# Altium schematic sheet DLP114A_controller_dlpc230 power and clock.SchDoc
size 558 x 431 mm; Date: Not shown in title block; ApprovedBy: Not shown in title block; CheckedBy: Not shown in title block; Author: Not shown in title block; CompanyName: Not shown in title block; Engineer: Not shown in title block; Organization: Not shown in title block; Address1: Not shown in title block; Address2: Not shown in title block; Address3: Not shown in title block; Address4: Not shown in title block; DocumentNumber: 2; Revision: Use project parameter SCH_Rev; SheetNumber: 2; SheetTotal: 7; PageSetup: Record=PageOptions¦CenterHorizontal=True¦CenterVertical=True¦PrintScale=0.69¦XCorrection=1.00¦YCorrection=1.00¦PrintKind=0¦BorderSize=5000000¦LeftOffset=0¦BottomOffset=0¦Orientation=2¦PaperLength=1000¦PaperWidth=1000¦Scale=100¦PaperSource=15¦PrintQuality=600¦MediaType=1¦DitherType=10¦PaperKind=Letter¦PrintScaleMode=1
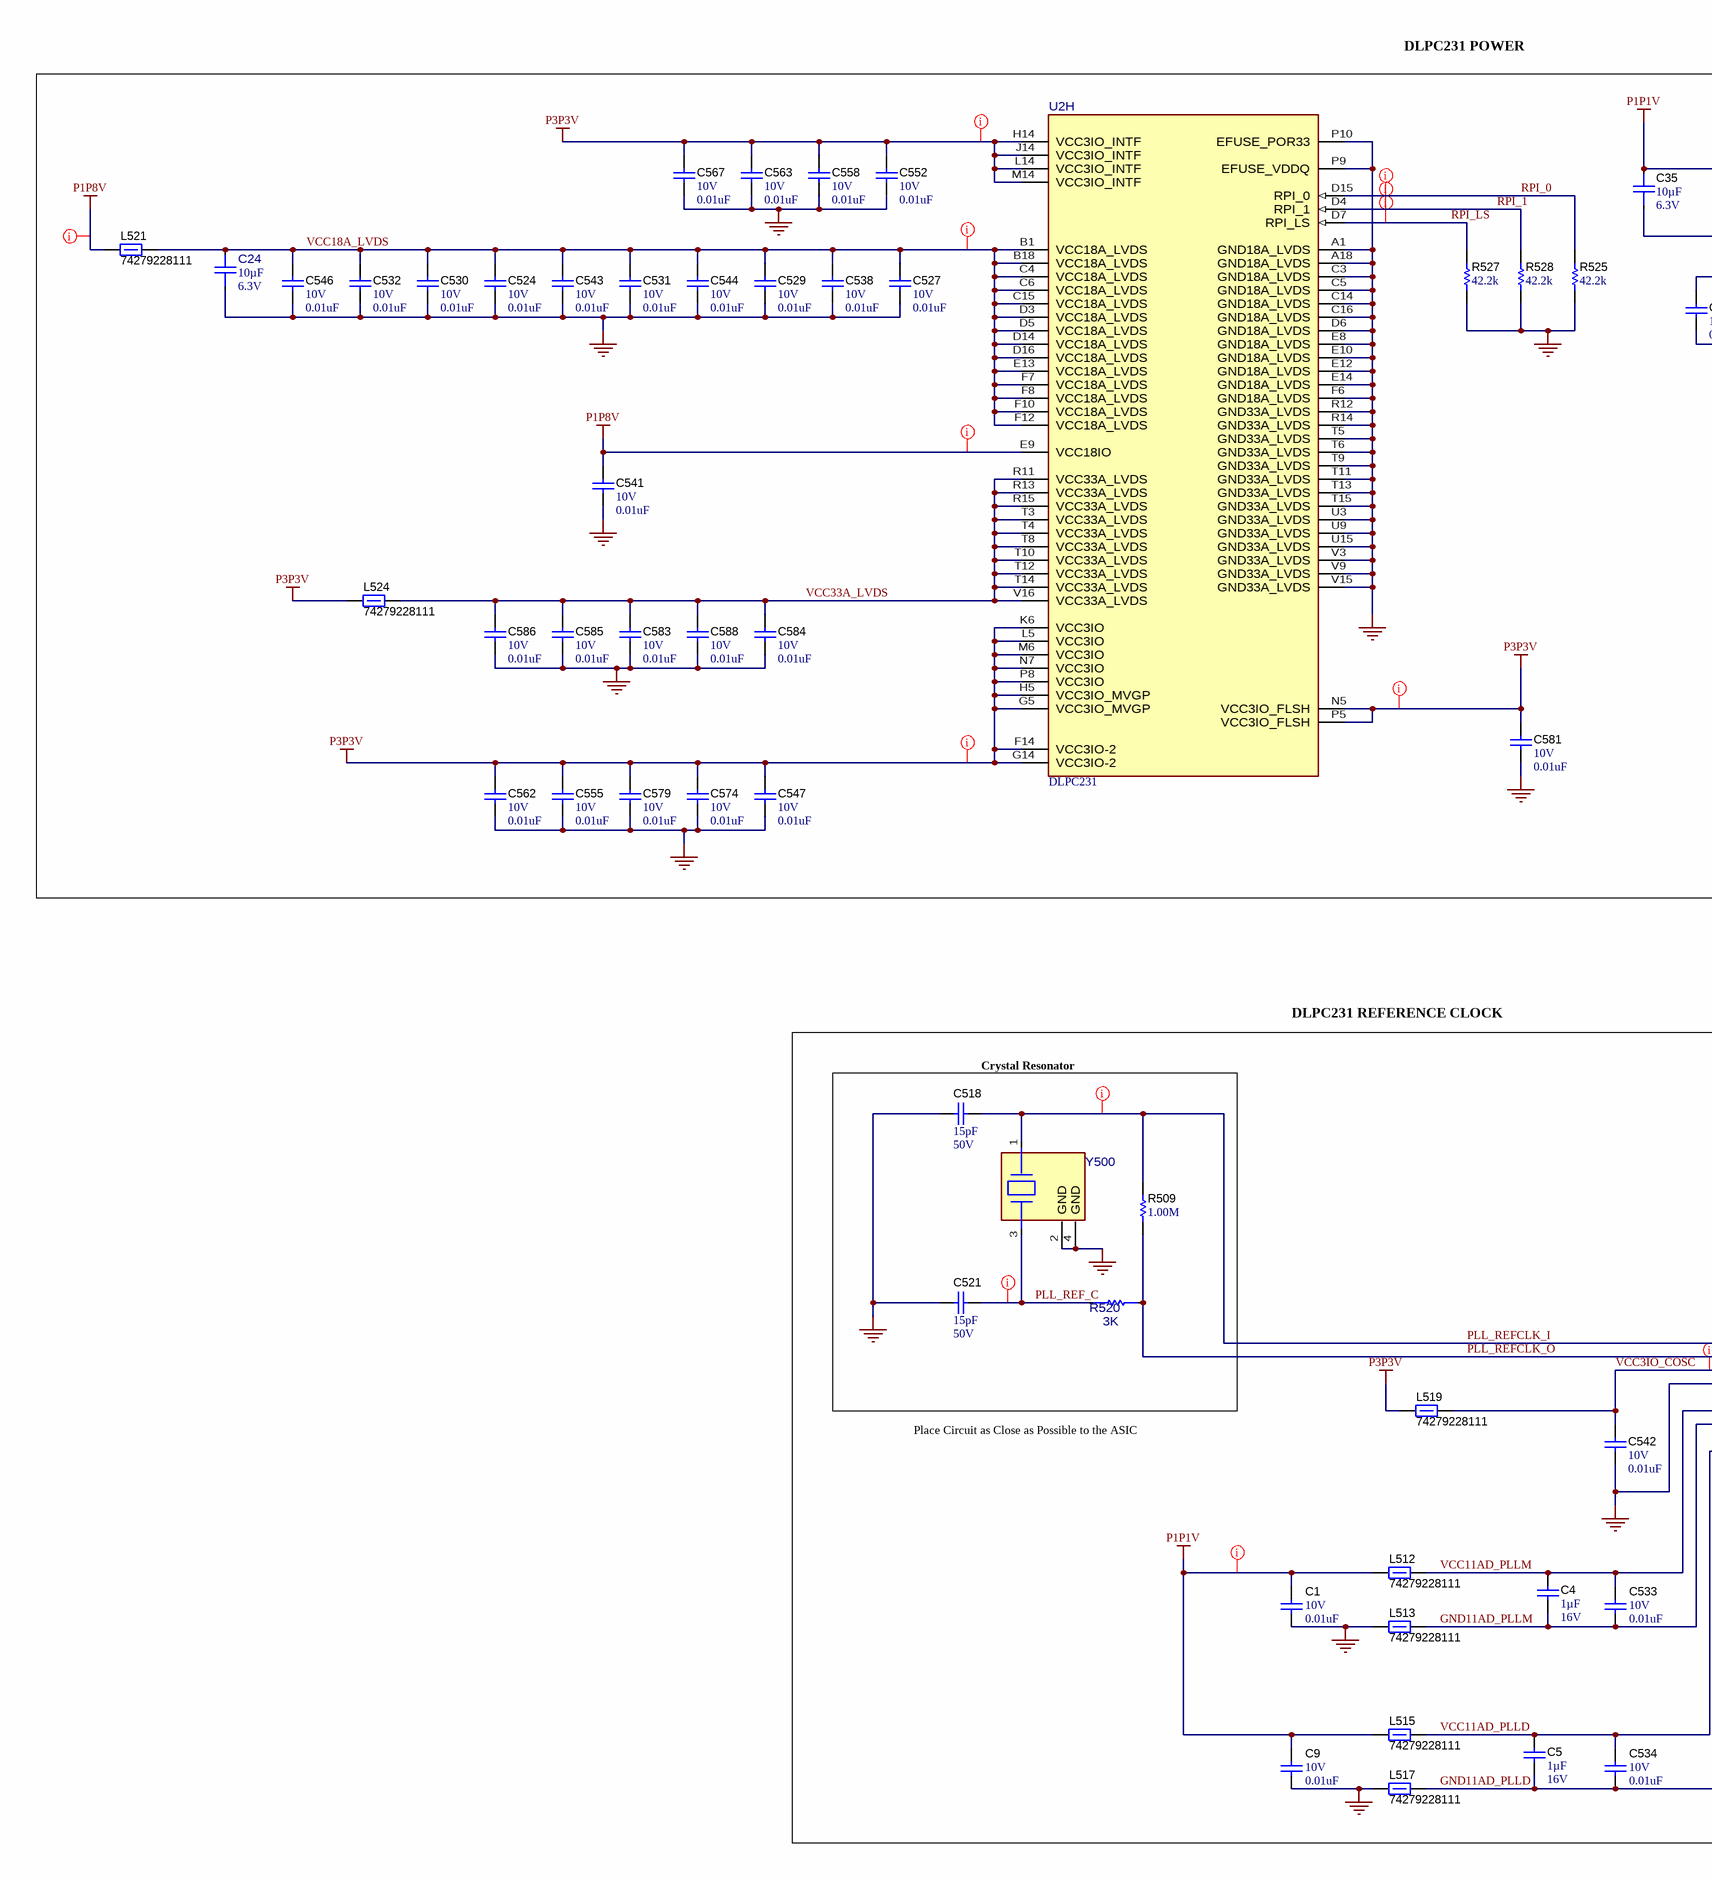
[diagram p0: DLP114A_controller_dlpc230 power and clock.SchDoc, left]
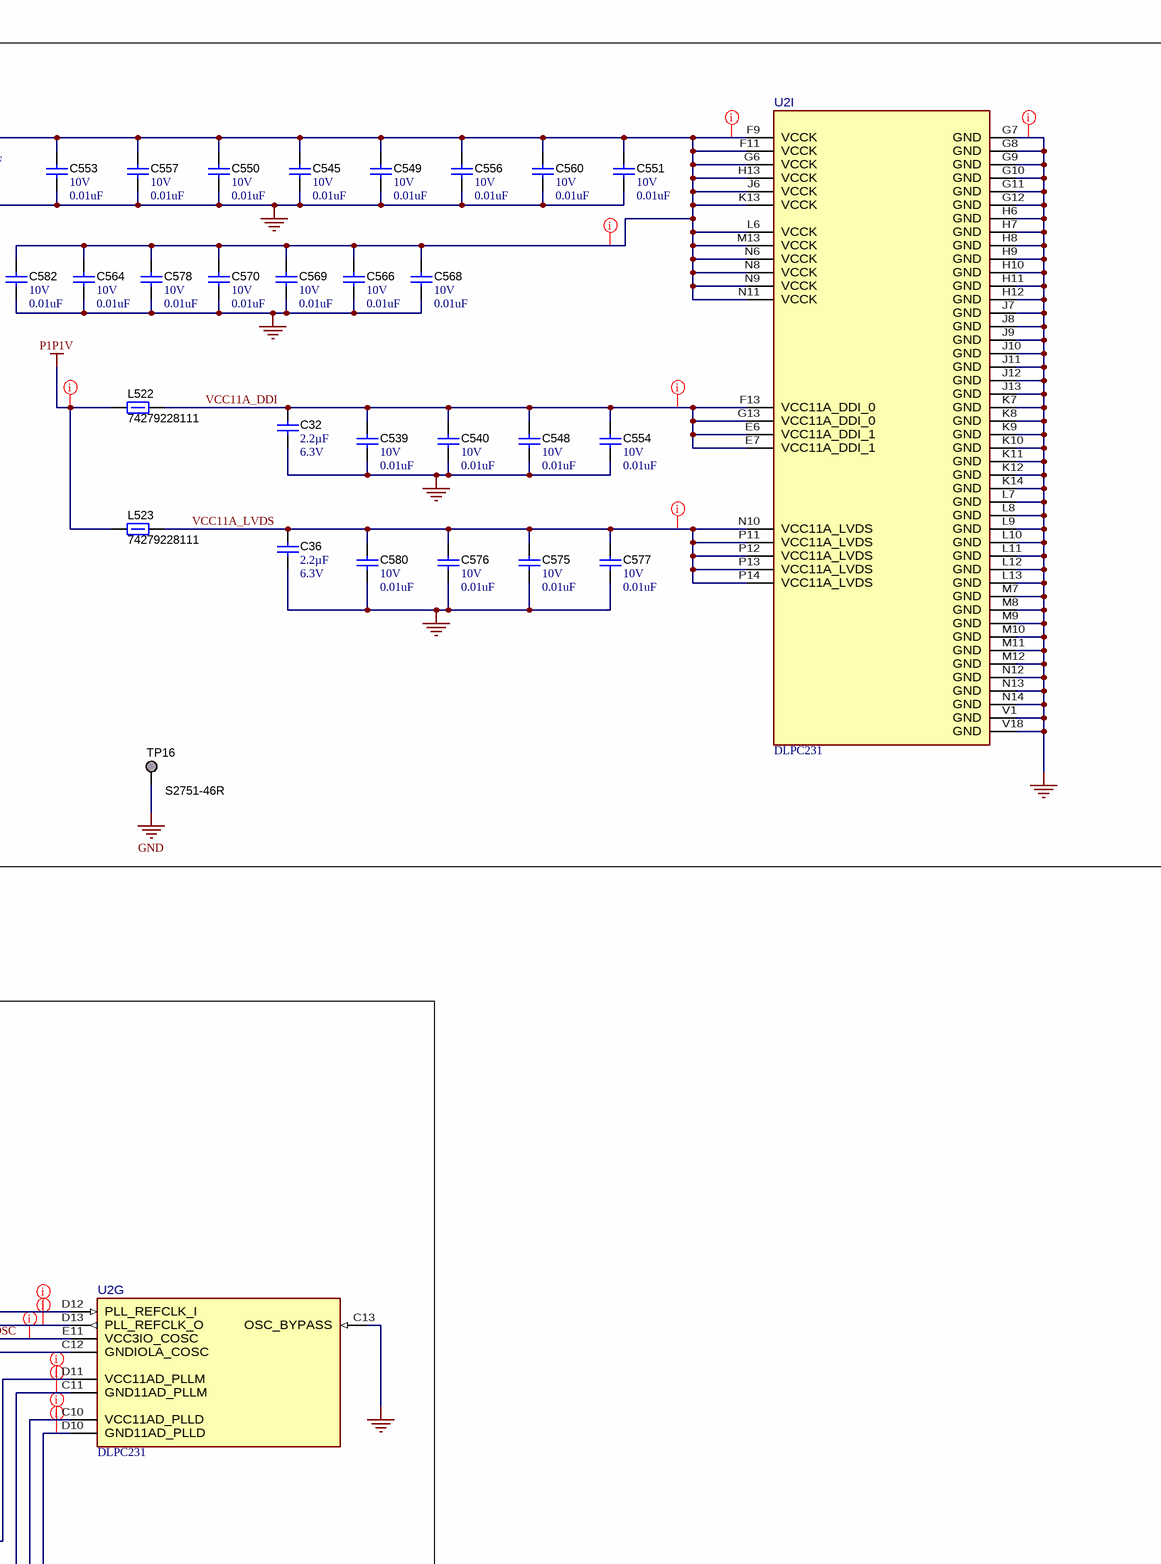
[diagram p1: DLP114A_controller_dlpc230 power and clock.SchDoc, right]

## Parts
C1  VDC_V: 10V  ValueDisplayed: 0.01uF  [0201_033]  (hidden comment: CGA1A2X7R1A103K030BA)
C4  Cap_F: 1µF  VDC_V: 16V  [0603]  (hidden comment: GCM188R71C105KA64D)
C5  Cap_F: 1µF  VDC_V: 16V  [0603]  (hidden comment: GCM188R71C105KA64D)
C9  VDC_V: 10V  ValueDisplayed: 0.01uF  [0201_033]  (hidden comment: CGA1A2X7R1A103K030BA)
C24  Cap_F: 10µF  VDC_V: 6.3V  [FP-CGA4J1X7R0J106K125AC_0805-MFG]  (hidden comment: CGA4J1X7R0J106K125AC)
C32  Cap_F: 2.2µF  VDC_V: 6.3V  [0603]  (hidden comment: GCM188R70J225KE22D)
C35  Cap_F: 10µF  VDC_V: 6.3V  [FP-CGA4J1X7R0J106K125AC_0805-MFG]  (hidden comment: CGA4J1X7R0J106K125AC)
C36  Cap_F: 2.2µF  VDC_V: 6.3V  [0603]  (hidden comment: GCM188R70J225KE22D)
C518  ValueDisplayed: 15pF  VDC_V: 50V  [0402]  (hidden comment: CGA2B2C0G1H150J050BA)
C521  ValueDisplayed: 15pF  VDC_V: 50V  [0402]  (hidden comment: CGA2B2C0G1H150J050BA)
C524  VDC_V: 10V  ValueDisplayed: 0.01uF  [0201_033]  (hidden comment: CGA1A2X7R1A103K030BA)
C527  VDC_V: 10V  ValueDisplayed: 0.01uF  [0201_033]  (hidden comment: CGA1A2X7R1A103K030BA)
C529  VDC_V: 10V  ValueDisplayed: 0.01uF  [0201_033]  (hidden comment: CGA1A2X7R1A103K030BA)
C530  VDC_V: 10V  ValueDisplayed: 0.01uF  [0201_033]  (hidden comment: CGA1A2X7R1A103K030BA)
C531  VDC_V: 10V  ValueDisplayed: 0.01uF  [0201_033]  (hidden comment: CGA1A2X7R1A103K030BA)
C532  VDC_V: 10V  ValueDisplayed: 0.01uF  [0201_033]  (hidden comment: CGA1A2X7R1A103K030BA)
C533  VDC_V: 10V  ValueDisplayed: 0.01uF  [0201_033]  (hidden comment: CGA1A2X7R1A103K030BA)
C534  VDC_V: 10V  ValueDisplayed: 0.01uF  [0201_033]  (hidden comment: CGA1A2X7R1A103K030BA)
C538  VDC_V: 10V  ValueDisplayed: 0.01uF  [0201_033]  (hidden comment: CGA1A2X7R1A103K030BA)
C539  VDC_V: 10V  ValueDisplayed: 0.01uF  [0201_033]  (hidden comment: CGA1A2X7R1A103K030BA)
C540  VDC_V: 10V  ValueDisplayed: 0.01uF  [0201_033]  (hidden comment: CGA1A2X7R1A103K030BA)
C541  VDC_V: 10V  ValueDisplayed: 0.01uF  [0201_033]  (hidden comment: CGA1A2X7R1A103K030BA)
C542  VDC_V: 10V  ValueDisplayed: 0.01uF  [0201_033]  (hidden comment: CGA1A2X7R1A103K030BA)
C543  VDC_V: 10V  ValueDisplayed: 0.01uF  [0201_033]  (hidden comment: CGA1A2X7R1A103K030BA)
C544  VDC_V: 10V  ValueDisplayed: 0.01uF  [0201_033]  (hidden comment: CGA1A2X7R1A103K030BA)
C545  VDC_V: 10V  ValueDisplayed: 0.01uF  [0201_033]  (hidden comment: CGA1A2X7R1A103K030BA)
C546  VDC_V: 10V  ValueDisplayed: 0.01uF  [0201_033]  (hidden comment: CGA1A2X7R1A103K030BA)
C547  VDC_V: 10V  ValueDisplayed: 0.01uF  [0201_033]  (hidden comment: CGA1A2X7R1A103K030BA)
C548  VDC_V: 10V  ValueDisplayed: 0.01uF  [0201_033]  (hidden comment: CGA1A2X7R1A103K030BA)
C549  VDC_V: 10V  ValueDisplayed: 0.01uF  [0201_033]  (hidden comment: CGA1A2X7R1A103K030BA)
C550  VDC_V: 10V  ValueDisplayed: 0.01uF  [0201_033]  (hidden comment: CGA1A2X7R1A103K030BA)
C551  VDC_V: 10V  ValueDisplayed: 0.01uF  [0201_033]  (hidden comment: CGA1A2X7R1A103K030BA)
C552  VDC_V: 10V  ValueDisplayed: 0.01uF  [0201_033]  (hidden comment: CGA1A2X7R1A103K030BA)
C553  VDC_V: 10V  ValueDisplayed: 0.01uF  [0201_033]  (hidden comment: CGA1A2X7R1A103K030BA)
C554  VDC_V: 10V  ValueDisplayed: 0.01uF  [0201_033]  (hidden comment: CGA1A2X7R1A103K030BA)
C555  VDC_V: 10V  ValueDisplayed: 0.01uF  [0201_033]  (hidden comment: CGA1A2X7R1A103K030BA)
C556  VDC_V: 10V  ValueDisplayed: 0.01uF  [0201_033]  (hidden comment: CGA1A2X7R1A103K030BA)
C557  VDC_V: 10V  ValueDisplayed: 0.01uF  [0201_033]  (hidden comment: CGA1A2X7R1A103K030BA)
C558  VDC_V: 10V  ValueDisplayed: 0.01uF  [0201_033]  (hidden comment: CGA1A2X7R1A103K030BA)
C560  VDC_V: 10V  ValueDisplayed: 0.01uF  [0201_033]  (hidden comment: CGA1A2X7R1A103K030BA)
C562  VDC_V: 10V  ValueDisplayed: 0.01uF  [0201_033]  (hidden comment: CGA1A2X7R1A103K030BA)
C563  VDC_V: 10V  ValueDisplayed: 0.01uF  [0201_033]  (hidden comment: CGA1A2X7R1A103K030BA)
C564  VDC_V: 10V  ValueDisplayed: 0.01uF  [0201_033]  (hidden comment: CGA1A2X7R1A103K030BA)
C566  VDC_V: 10V  ValueDisplayed: 0.01uF  [0201_033]  (hidden comment: CGA1A2X7R1A103K030BA)
C567  VDC_V: 10V  ValueDisplayed: 0.01uF  [0201_033]  (hidden comment: CGA1A2X7R1A103K030BA)
C568  VDC_V: 10V  ValueDisplayed: 0.01uF  [0201_033]  (hidden comment: CGA1A2X7R1A103K030BA)
C569  VDC_V: 10V  ValueDisplayed: 0.01uF  [0201_033]  (hidden comment: CGA1A2X7R1A103K030BA)
C570  VDC_V: 10V  ValueDisplayed: 0.01uF  [0201_033]  (hidden comment: CGA1A2X7R1A103K030BA)
C574  VDC_V: 10V  ValueDisplayed: 0.01uF  [0201_033]  (hidden comment: CGA1A2X7R1A103K030BA)
C575  VDC_V: 10V  ValueDisplayed: 0.01uF  [0201_033]  (hidden comment: CGA1A2X7R1A103K030BA)
C576  VDC_V: 10V  ValueDisplayed: 0.01uF  [0201_033]  (hidden comment: CGA1A2X7R1A103K030BA)
C577  VDC_V: 10V  ValueDisplayed: 0.01uF  [0201_033]  (hidden comment: CGA1A2X7R1A103K030BA)
C578  VDC_V: 10V  ValueDisplayed: 0.01uF  [0201_033]  (hidden comment: CGA1A2X7R1A103K030BA)
C579  VDC_V: 10V  ValueDisplayed: 0.01uF  [0201_033]  (hidden comment: CGA1A2X7R1A103K030BA)
C580  VDC_V: 10V  ValueDisplayed: 0.01uF  [0201_033]  (hidden comment: CGA1A2X7R1A103K030BA)
C581  VDC_V: 10V  ValueDisplayed: 0.01uF  [0201_033]  (hidden comment: CGA1A2X7R1A103K030BA)
C582  VDC_V: 10V  ValueDisplayed: 0.01uF  [0201_033]  (hidden comment: CGA1A2X7R1A103K030BA)
C583  VDC_V: 10V  ValueDisplayed: 0.01uF  [0201_033]  (hidden comment: CGA1A2X7R1A103K030BA)
C584  VDC_V: 10V  ValueDisplayed: 0.01uF  [0201_033]  (hidden comment: CGA1A2X7R1A103K030BA)
C585  VDC_V: 10V  ValueDisplayed: 0.01uF  [0201_033]  (hidden comment: CGA1A2X7R1A103K030BA)
C586  VDC_V: 10V  ValueDisplayed: 0.01uF  [0201_033]  (hidden comment: CGA1A2X7R1A103K030BA)
C588  VDC_V: 10V  ValueDisplayed: 0.01uF  [0201_033]  (hidden comment: CGA1A2X7R1A103K030BA)
L512  74279228111  [0603]
L513  74279228111  [0603]
L515  74279228111  [0603]
L517  74279228111  [0603]
L519  74279228111  [0603]
L521  74279228111  [0603]
L522  74279228111  [0603]
L523  74279228111  [0603]
L524  74279228111  [0603]
R509  ValueDisplayed: 1.00M  [0402]  (hidden comment: CRCW04021M00FKED)
R520  3K  [FP-ERJ-2RKF3001X_0402-MFG]
R525  ValueDisplayed: 42.2k  [0402]  (hidden comment: CRCW040242K2FKED)
R527  ValueDisplayed: 42.2k  [0402]  (hidden comment: CRCW040242K2FKED)
R528  ValueDisplayed: 42.2k  [0402]  (hidden comment: CRCW040242K2FKED)
TP16  S2751-46R  [Harwin_S2751-46R]  (no BOM)
U2  DLPC231  [ZEK0324A-MFG]  (parts G,H,I of 9)
Y500  AM16070006  [FP-AM16070006_SMT_XTAL_3MM2_2MM5-MFG]  (value not drawn)

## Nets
GND: C1.2 C9.2 C24.1 C32.2 C35.1 C36.2 C518.2 C521.2 C524.2 C527.2 C529.2 C530.2 C531.2 C532.2 C538.2 C539.2 C540.2 C541.2 C542.2 C543.2 C544.2 C545.2 C546.2 C547.2 C548.2 C549.2 C550.2 C551.2 C552.2 C553.2 C554.2 C555.2 C556.2 C557.2 C558.2 C560.2 C562.2 C563.2 C564.2 C566.2 C567.2 C568.2 C569.2 C570.2 C574.2 C575.2 C576.2 C577.2 C578.2 C579.2 C580.2 C581.2 C582.2 C583.2 C584.2 C585.2 C586.2 C588.2 L513.1 L517.1 R525.1 R527.1 R528.1 TP16.1 U2.A1(GND18A_LVDS) U2.A18(GND18A_LVDS) U2.C3(GND18A_LVDS) U2.C5(GND18A_LVDS) U2.C12(GNDIOLA_COSC) U2.C13(OSC_BYPASS) U2.C14(GND18A_LVDS) U2.C16(GND18A_LVDS) U2.D6(GND18A_LVDS) U2.E8(GND18A_LVDS) U2.E10(GND18A_LVDS) U2.E12(GND18A_LVDS) U2.E14(GND18A_LVDS) U2.F6(GND18A_LVDS) U2.G7(GND) U2.G8(GND) U2.G9(GND) U2.G10(GND) U2.G11(GND) U2.G12(GND) U2.H6(GND) U2.H7(GND) U2.H8(GND) U2.H9(GND) U2.H10(GND) U2.H11(GND) U2.H12(GND) U2.J7(GND) U2.J8(GND) U2.J9(GND) U2.J10(GND) U2.J11(GND) U2.J12(GND) U2.J13(GND) U2.K7(GND) U2.K8(GND) U2.K9(GND) U2.K10(GND) U2.K11(GND) U2.K12(GND) U2.K14(GND) U2.L7(GND) U2.L8(GND) U2.L9(GND) U2.L10(GND) U2.L11(GND) U2.L12(GND) U2.L13(GND) U2.M7(GND) U2.M8(GND) U2.M9(GND) U2.M10(GND) U2.M11(GND) U2.M12(GND) U2.N12(GND) U2.N13(GND) U2.N14(GND) U2.P9(EFUSE_VDDQ) U2.P10(EFUSE_POR33) U2.R12(GND33A_LVDS) U2.R14(GND33A_LVDS) U2.T5(GND33A_LVDS) U2.T6(GND33A_LVDS) U2.T9(GND33A_LVDS) U2.T11(GND33A_LVDS) U2.T13(GND33A_LVDS) U2.T15(GND33A_LVDS) U2.U3(GND33A_LVDS) U2.U9(GND33A_LVDS) U2.U15(GND33A_LVDS) U2.V1(GND) U2.V3(GND33A_LVDS) U2.V9(GND33A_LVDS) U2.V15(GND33A_LVDS) U2.V18(GND) Y500.2(GND) Y500.4(GND)
P1P1V: C1.1 C9.1 C35.2 C545.1 C549.1 C550.1 C551.1 C553.1 C556.1 C557.1 C560.1 C564.1 C566.1 C568.1 C569.1 C570.1 C578.1 C582.1 L512.1 L515.1 L522.1 L523.1 U2.F9(VCCK) U2.F11(VCCK) U2.G6(VCCK) U2.H13(VCCK) U2.J6(VCCK) U2.K13(VCCK) U2.L6(VCCK) U2.M13(VCCK) U2.N6(VCCK) U2.N8(VCCK) U2.N9(VCCK) U2.N11(VCCK)
P1P8V: C541.1 L521.1 U2.E9(VCC18IO)
P3P3V: C547.1 C552.1 C555.1 C558.1 C562.1 C563.1 C567.1 C574.1 C579.1 C581.1 L519.1 L524.2 U2.F14(VCC3IO-2) U2.G5(VCC3IO_MVGP) U2.G14(VCC3IO-2) U2.H5(VCC3IO_MVGP) U2.H14(VCC3IO_INTF) U2.J14(VCC3IO_INTF) U2.K6(VCC3IO) U2.L5(VCC3IO) U2.L14(VCC3IO_INTF) U2.M6(VCC3IO) U2.M14(VCC3IO_INTF) U2.N5(VCC3IO_FLSH) U2.N7(VCC3IO) U2.P5(VCC3IO_FLSH) U2.P8(VCC3IO)
GND11AD_PLLD: C5.2 C534.2 L517.2 U2.D10(GND11AD_PLLD)
GND11AD_PLLM: C4.2 C533.2 L513.2 U2.C11(GND11AD_PLLM)
PLL_REF_C: C521.1 R520.1 Y500.3
PLL_REFCLK_I: C518.1 R509.2 U2.D12(PLL_REFCLK_I) Y500.1
PLL_REFCLK_O: R509.1 R520.2 U2.D13(PLL_REFCLK_O)
RPI_0: R525.2 U2.D15(RPI_0)
RPI_1: R528.2 U2.D4(RPI_1)
RPI_LS: R527.2 U2.D7(RPI_LS)
VCC3IO_COSC: C542.1 L519.2 U2.E11(VCC3IO_COSC)
VCC11A_DDI: C32.1 C539.1 C540.1 C548.1 C554.1 L522.2 U2.E6(VCC11A_DDI_1) U2.E7(VCC11A_DDI_1) U2.F13(VCC11A_DDI_0) U2.G13(VCC11A_DDI_0)
VCC11A_LVDS: C36.1 C575.1 C576.1 C577.1 C580.1 L523.2 U2.N10(VCC11A_LVDS) U2.P11(VCC11A_LVDS) U2.P12(VCC11A_LVDS) U2.P13(VCC11A_LVDS) U2.P14(VCC11A_LVDS)
VCC11AD_PLLD: C5.1 C534.1 L515.2 U2.C10(VCC11AD_PLLD)
VCC11AD_PLLM: C4.1 C533.1 L512.2 U2.D11(VCC11AD_PLLM)
VCC18A_LVDS: C24.2 C524.1 C527.1 C529.1 C530.1 C531.1 C532.1 C538.1 C543.1 C544.1 C546.1 L521.2 U2.B1(VCC18A_LVDS) U2.B18(VCC18A_LVDS) U2.C4(VCC18A_LVDS) U2.C6(VCC18A_LVDS) U2.C15(VCC18A_LVDS) U2.D3(VCC18A_LVDS) U2.D5(VCC18A_LVDS) U2.D14(VCC18A_LVDS) U2.D16(VCC18A_LVDS) U2.E13(VCC18A_LVDS) U2.F7(VCC18A_LVDS) U2.F8(VCC18A_LVDS) U2.F10(VCC18A_LVDS) U2.F12(VCC18A_LVDS)
VCC33A_LVDS: C583.1 C584.1 C585.1 C586.1 C588.1 L524.1 U2.R11(VCC33A_LVDS) U2.R13(VCC33A_LVDS) U2.R15(VCC33A_LVDS) U2.T3(VCC33A_LVDS) U2.T4(VCC33A_LVDS) U2.T8(VCC33A_LVDS) U2.T10(VCC33A_LVDS) U2.T12(VCC33A_LVDS) U2.T14(VCC33A_LVDS) U2.V16(VCC33A_LVDS)

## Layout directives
net class 50OHM: GND11AD_PLLD, GND11AD_PLLM, PLL_REF_C, PLL_REFCLK_I, PLL_REFCLK_O, RPI_0, RPI_1, RPI_LS, VCC11AD_PLLD, VCC11AD_PLLM
net class POWER: GND, P1P1V, P1P8V, P3P3V, VCC11A_DDI, VCC11A_LVDS, VCC18A_LVDS
net class Voltage Spacing (15Mils): VCC3IO_COSC

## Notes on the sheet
- DLPC231 POWER
- DLPC231 REFERENCE CLOCK INTERFACE
- (near C518) Crystal Resonator
- Place Circuit as Close as Possible to the ASIC

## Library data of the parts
C1 C9 C524 C527 C529-C534 C538-C558 C560 C562-C564 C566-C570 C574-C586 C588 = CMP-0009642-3: CAP, CERM, 0.01 uF, 10 V, +/- 10%, X7R, AEC-Q200 Grade 1, 0201; Manufacturer: TDK; TaMin_C: -55°C; ESR_ohm: 0.2802; Polarized: N; SizeAreaWB_mm2: 2.08; Value1: 0.280214 ohm; U/M: EA; Value: 0.01uF; TaMax_C: 125°C; SizeZ_mm: 0.33; SizeX_mm: 0.6; SizeY_mm: 0.3; SizeArea_mm2: 0.18; AEC Qualified: Y; Cap_F: 10nF; IRMS_A: 245.718mA; AEC Grade: 1; AEC Category: Q200
C4 C5 = CMP-0007136-5: CAP, CERM, 1 uF, 16 V, +/- 10%, X7R, AEC-Q200 Grade 1, 0603; Manufacturer: MuRata; TaMin_C: -55°C; Polarized: N; SizeAreaWB_mm2: 4.68; Value1: Unknown; U/M: EA; Value: 1uF; TaMax_C: 125°C; SizeZ_mm: 1; SizeX_mm: 1.6; SizeY_mm: 0.8; SizeArea_mm2: 1.28; AEC Qualified: Y; AEC Category: Q200
C24 C35 = CMP-0093813-1: Cap Ceramic 10uF 6.3V X7R 10% Pad SMD 0805 +125°C Automotive T/R; Manufacturer: TDK Corporation; Value: 10µF; TempCo: 15%; AEC Qualified: Yes; AEC Grade: Grade 1; Tolerance_%: 0.1%; SizeZ_mm: 1.45mm
C32 C36 = CMP-0007134-5: CAP, CERM, 2.2 uF, 6.3 V, +/- 10%, X7R, AEC-Q200 Grade 1, 0603; Manufacturer: MuRata; TaMin_C: -55°C; Polarized: N; SizeAreaWB_mm2: 4.68; Value1: Unknown; U/M: EA; Value: 2.2uF; TaMax_C: 125°C; SizeZ_mm: 1; SizeX_mm: 1.6; SizeY_mm: 0.8; SizeArea_mm2: 1.28; AEC Qualified: Y; AEC Category: Q200
C518 C521 = CMP-0860829-1: CAP, CERM, 15 pF, 50 V,+/- 5%, C0G/NP0, AEC-Q200 Grade 1, 0402; Manufacturer: TDK; SizeZ_mm: 0.6; Polarized: N; TaMin_C: -55°C; SizeX_mm: 1; AEC Qualified: Y; SizeY_mm: 0.5; Value: 15pF; AEC Category: Q200; SizeAreaWB_mm2: 3; TaMax_C: 125°C; U/M: EA
L512 L513 L515 L517 L519 L521-L524 = CMP-0003154-1: Ferrite Bead, 110 ohm @ 100 MHz, 4.1 A, 0603; Manufacturer: Wurth Elektronik; Ztyp@1GHz_Ohm: 51.875; ZTyp@100MHz_Ohm: 110; SizeAreaWB_mm2: 4.68; DCR_ohm: 14.5m; Value1: 0.0145 ohm; Value: 110 ohm; Imax_A: 4.1A; SizeZ_mm: 1; SizeX_mm: 1.6; SizeY_mm: 0.8; SizeArea_mm2: 1.28
R509 = CMP-0026100-2: RES, 1.00 M, 1%, 0.063 W, AEC-Q200 Grade 0, 0402; Manufacturer: Vishay-Dale; Power_W: 63mW; TempCo: 100 ppm/C; Value_Code: 1M00; Value: 1.00Meg; EIA_Code: E96; Res_ohm: 1M; SizeX_mm: 1; SizeY_mm: 0.5; SizeZ_mm: 0.6; Value2: 0.063W; AEC Qualified: Y; VDC_V: 50V; AEC Category: Q200; AEC Grade: 0
R520 = CMP-0090071-1: Res Thick Film 0402 3K Ohm 1% 0.1W(1/10W) +/-100ppm/C Molded SMD Automotive Punched T/R; PartNumber: ERJ-2RKF3001X; Manufacturer: Panasonic; AEC Qualified: Yes; Power_W: 100mW; SizeZ_mm: 0.4mm; VDC_V: 50V; AEC Grade: Grade 0; TempCo: 100ppm/°C
R525 R527 R528 = CMP-0026375-2: RES, 42.2 k, 1%, 0.063 W, AEC-Q200 Grade 0, 0402; Manufacturer: Vishay-Dale; Power_W: 63mW; TempCo: 100 ppm/C; Value_Code: 42k2; Value: 42.2k; EIA_Code: E96; SizeX_mm: 1; SizeY_mm: 0.5; SizeZ_mm: 0.6; Value2: 0.063W; AEC Qualified: Y; VDC_V: 50V; AEC Category: Q200; AEC Grade: 0
TP16 = CMP-0003968-1: Test Point, SMT; Manufacturer: Harwin
U2 = CMP-0096130-1: Manufacturer: Texas Instruments; Standoff Height: 0.35mm; SizeZ_mm: 1.5mm
Y500 = CMP-0087311-1: SMD SEAM SEALING X'TAL 3.2×2.5; Manufacturer: TXC Corporation; Load Capacitance: 10pF; AEC Grade: Grade 1; Frequency_Fixed: 16MHz; AEC Qualified: Yes; SizeZ_mm: 0.8mm; Frequency Stability: 50ppm; Frequency Tolerance: 10ppm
